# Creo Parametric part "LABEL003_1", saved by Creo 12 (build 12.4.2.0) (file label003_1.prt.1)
Units: Custom; MM, KILOGRAM, SECS

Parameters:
  PTC_WM_ITERATION = "0"
  PTC_WM_VERSION = "-.0"
  PTC_WM_LIFECYCLE_STATE = "In Work"
  PTC_WM_LIFECYCLE = "MO_CADDocument"
  PTC_WM_CREATED_BY = "Maximilian Roepper (Z0017RMS: MO)"
  PTC_WM_CREATED_ON = "18-Sep-26 11:36:42 AM"
  PTC_WM_MODIFIED_BY = "Maximilian Roepper (Z0017RMS: MO)"
  PTC_WM_MODIFIED_ON = "18-Sep-26 11:36:46 AM"
  PDMLINKNUMBER = "PDM000071455035"
  PTC_WM_NAME = "label003_1.prt"
  PTC_WM_NUMBER = "PDM000071455035"

Other parameters: WEIGHT, WEIGHT_FACTOR, WEIGHT_ADD, _MASS_TEMP, _DIFF_TEMP, MC_ERRORS, SUPPLIER

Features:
  1. coordinate system
  2. datum plane "PRT_YZ"
  3. datum plane "PRT_XY"
  4. datum plane "PRT_XZ"
  5. coordinate system
  6. datum axis
  7. datum axis
  8. datum axis
  9. coordinate system
  10. imported feature

Other named items: PRT, SIEMENS_MO, DRW_VIEW_ORG, PRT_X, PRT_Y, PRT_Z, CS0, ROUGH_GROB

Layers: 00_STD_CSYS-KSYS, 01_STD_PLANES-EBENEN, 02_STD_AXES-ACHSEN, 03_STD_CSYS-KSYS, 24_IMPORT_FEAT-IMPORT_KE

Surfaces: 6 plane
